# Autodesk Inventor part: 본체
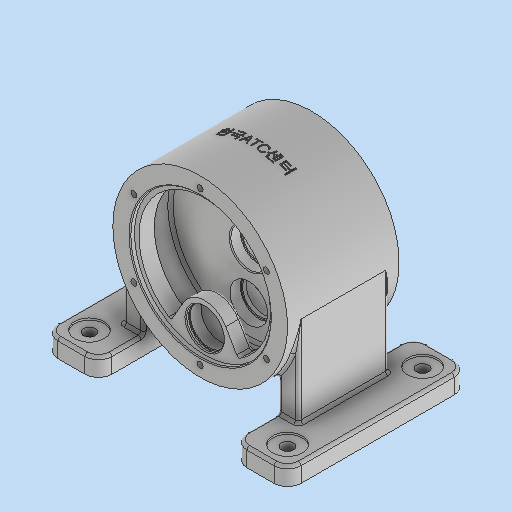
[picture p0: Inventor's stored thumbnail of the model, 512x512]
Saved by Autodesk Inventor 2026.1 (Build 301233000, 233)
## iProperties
Created: 2025-12
Part Number: 본체
Material: 일반
Document SubType Name: Modeling
Designer: PC-30
Density: 1 g/cm^3
Appearance: 기본값
Author: PC-30
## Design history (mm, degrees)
sketch "스케치1"
  geometry: L1 (-135, 100)-(-75, 100); L2 (-75, 100)-(-75, -100); L3 (-75, -100)-(-135, -100); L4 (-135, -100)-(-135, 100); L5 (-135, 100)-(-75, -100); L6 (-75, 100)-(-135, -100); 3 further points
  constraints: 12 end point, 3 midpoint, 2 parallel, 1 horizontal, 1 horizontal alignment, 1 perpendicular
  dimensions: "d0" = 200 distance from line of point (-105, -100) L1; "d1" = 60 distance between parallel lines of L2 L4; "d2" = 75 distance from line of L2 point (0, 0)
extrude "돌출1" new body sketch "스케치1" distance "d3" = 20; taper "d4" = 0 deg
sketch "스케치2"
  geometry: C1 r 97 at (0, 120); 1 further point
  constraints: 1 centre point, 1 vertical alignment
  dimensions: "d5" = 194 diameter of C1; "d6" = 120 distance of point (0, 0) C1.centre
extrude "돌출2" join sketch "스케치2" stored distance "d7" = 124; taper "d8" = 0 deg
sketch "스케치3"
  geometry: L1 (135, 20)-(75, 20) reference; L2 (97, 120)-(97, 20); L3 (75, 20)-(75, 58.486); A1 r 97 centre (0, 120) between (97, 120) and (75, 58.486) reference; 1 further point
  constraints: 4 end point, 2 point on circle, 1 parallel, 1 perpendicular, 1 point on line, 1 tangent
extrude "돌출3" join sketch "스케치3" stored distance "d9" = 100; taper "d10" = 0 deg
sketch "스케치4"
  geometry: L1 (75, 8)-(47.403, 23.933); L2 (75, 0)-(75, 20) reference; L3 (75, 0)-(135, 0) reference; C1 r 97 at (0, 120) reference; 1 further point
  constraints: 2 end point, 1 point on line
  dimensions: "d11" = 8 distance from line of L1.start L3; "d12" = 60 deg angle of L1 L2
feature "리브1" sketch "스케치4" dims "d13" = 1, "d14" = 12, "d15" = 0, "d16" = 0, "d17" = 1, "d18" = 1
sketch "스케치5"
  geometry: L1 (-62, 198)-(-57, 198); L2 (-57, 198)-(-57, 193); L3 (-57, 193)-(-40, 193); L4 (-40, 193)-(-40, 207); L5 (-40, 207)-(-8, 207); L6 (-8, 207)-(-8, 193); L7 (-8, 193)-(-8, 141); L8 (-8, 141)-(4, 141); L9 (4, 141)-(4, 139); L10 (4, 139)-(8, 139); L11 (8, 139)-(8, 207); L12 (8, 207)-(40, 207); L13 (40, 207)-(40, 193); L14 (40, 193)-(57, 193); L15 (57, 193)-(57, 198); L16 (57, 198)-(62, 198); L17 (-62, 217)-(-62, 23) reference; L18 (62, 23)-(62, 217) reference; L19 (-62, 120)-(62, 120); 10 further points
  constraints: 34 end point, 12 perpendicular, 10 midpoint, 7 point on line, 1 horizontal
  dimensions: "d19" = 156 diameter of point (-58.459, 198) L19; "d20" = 5 distance from line of L17 point (-57, 195.5); "d21" = 17 distance between parallel lines of L4 L2; "d22" = 146 diameter of L3 L19; "d23" = 174 diameter of point (-24, 207) L19; "d24" = 32 distance from line of L6 point (-40, 200); "d25" = 156 diameter of point (59.5, 198) L19; "d26" = 5 distance from line of L18 point (57, 195.5); "d27" = 146 diameter of point (48.5, 193) L19; "d28" = 17 distance of L13.end L14.end; "d29" = 32 distance between parallel lines of L13 L11; "d30" = 42 diameter of point (-2, 141) L19; "d31" = 38 diameter of point (6, 139) L19; "d32" = 66 distance between parallel lines of L9 L17
revolve "회전1" sketch "스케치5" stored, may be unused: angle "d33" = 90 deg
sketch "스케치6"
  geometry: L1 (-23.383, -39)-(-37.148, -62.842); L2 (23.383, -39)-(37.148, -62.842); L3 (0, 0)-(0, -120); A1 r 73 centre (0, 0) between (37.148, -62.842) and (-37.148, -62.842) reference; A2 r 27 centre (0, -52.5) between (23.383, -39) and (-23.383, -39)
  constraints: 6 end point, 4 point on circle, 2 tangent, 1 centre point, 1 point on line, 1 vertical
  dimensions: "d34" = 52.5 distance of L3.start A2.centre; "d35" = 54 diameter of A2; "d36" = 60 deg angle of L2 L1; "d37" = 30 deg angle of L1 L3
extrude "돌출4" join sketch "스케치6" distance "d38" = 17; taper "d39" = 0 deg
sketch "스케치7"
  geometry: L1 (-62, 42)-(-62, 198) reference; L2 (-57, 198)-(-57, 42) reference; L3 (-40, 57.158)-(-40, 81) reference; L4 (-40, 81)-(-40, 94.5) reference; L5 (-57, 88.5)-(-53.95, 88.5); L6 (-53.95, 88.5)-(-53.95, 89.75); L7 (-53.95, 89.75)-(-52, 89.75); L8 (-52, 89.75)-(-52, 88.5); L9 (-52, 88.5)-(-40, 88.5); L10 (-57, 67.5)-(-40, 67.5); 2 further points
  constraints: 12 end point, 6 point on line, 3 perpendicular, 1 horizontal, 1 midpoint, 1 parallel
  dimensions: "d40" = 52.5 distance from line of point (-62, 120) L10; "d41" = 42 diameter of L9 L10; "d42" = 44.5 diameter of L7 L10; "d43" = 12 distance between parallel lines of L8 L4; "d44" = 1.95 distance between parallel lines of L8 L6
revolve "회전2" sketch "스케치7" stored, may be unused: angle "d45" = 90 deg
sketch "스케치8"
  geometry: C1 r 21 at (0, -52.5) reference; 2 further points
  constraints: 1 coincident
hole "구멍1" sketch "스케치8" at (0, -52.5) diameter "d46" = 38; stored, may be unused: countersink angle "d50" = 90 deg, drill point angle "d52" = 118 deg; dims "d47" = 6, "d48" = 42, "d49" = 12, "d51" = 5
sketch "스케치9" dims "d53" = 170
  geometry: C1 r 97 at (0, 0) reference; 3 further points
  constraints: 2 vertical alignment, 3 other
hole "구멍2" sketch "스케치9" at (0, 85) diameter "d54" = 6.647; stored, may be unused: countersink angle "d58" = 90 deg, drill point angle "d60" = 118 deg; dims "d55" = 16, "d56" = 42, "d57" = 12, "d59" = 18
sketch "스케치10" dims "d64" = 170
  geometry: C1 r 97 at (0, 0) reference; 3 further points
  constraints: 2 vertical alignment, 3 other
hole "구멍3" sketch "스케치10" at (0, -85) diameter "d65" = 6.647; stored, may be unused: countersink angle "d69" = 90 deg, drill point angle "d71" = 118 deg; dims "d66" = 16, "d67" = 4, "d68" = 2, "d70" = 18
sketch "스케치11"
  geometry: L1 (60, -200)-(0, -200) reference; L2 (60, 0)-(60, -200) reference; 2 further points
  dimensions: "d72" = 25 distance from line of point (35, -175) L1; "d73" = 25 distance from line of point (35, -175) L2
hole "구멍4" sketch "스케치11" at (35, -175) diameter "d74" = 13.5; stored, may be unused: countersink angle "d78" = 90 deg, drill point angle "d80" = 118 deg; dims "d75" = 16, "d76" = 33, "d77" = 2, "d79" = 18
fillet "모깎기1" dims "d87" = 15
fillet "모깎기4" dims "d90" = 3
fillet "모깎기5" dims "d91" = 3
fillet "모깎기6" dims "d92" = 3
fillet "모깎기7" dims "d93" = 3
fillet "모깎기8" dims "d94" = 3
fillet "모깎기9" dims "d95" = 3
fillet "모깎기10" dims "d96" = 3
fillet "모깎기11" dims "d97" = 0.6
fillet "모깎기12" dims "d98" = 3
chamfer "모따기1" distance "d99" = 1; stored, may be unused: second distance "d100" = 2, angle "d101" = 45 deg
fillet "모깎기13" dims "d102" = 3
fillet "모깎기14" dims "d103" = 3
node "작업 평면1"
sketch "스케치12"
  geometry: L1 (-61.5, 25)-(61.5, 25); L2 (61.5, 25)-(61.5, -25); L3 (61.5, -25)-(-61.5, -25); L4 (-61.5, -25)-(-61.5, 25); L5 (-61.5, 0)-(61.5, 0); L6 (0, -25)-(0, 25); 2 further points
  constraints: 5 midpoint, 4 end point, 1 coincident, 2 other
  dimensions: "d105" = 50 distance between parallel lines of L1 L3; "d106" = 123 distance between parallel lines of L2 L4
feature "엠보싱1" sketch "스케치12" dims "d107" = 0.5, "d108" = 0
node "솔리드1"
mirror "미러1"
mirror "미러2"
pattern_circular "원형 패턴1" dims angle "d62" = 360 deg
pattern_linear "직사각형 패턴1" dims "d86" = 220
pattern_circular "원형 패턴2" dims angle "d110" = 360 deg
node "투영된 루프1"
feature "A9D066F2-1C7D-4E18-AEED-F7BC21143FA4" dims "d46" = 38, "d47" = 6, "d48" = 42, "d49" = 12, "d50" = 90 deg, "d51" = 5, "d52" = 118 deg
other parameters: "d104" = 274.75
